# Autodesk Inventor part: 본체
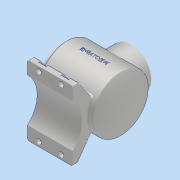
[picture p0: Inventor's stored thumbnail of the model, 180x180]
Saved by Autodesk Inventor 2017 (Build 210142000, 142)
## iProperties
Part Number: 본체
Material: 알루미늄 6061
Document SubType Name: Modeling
Designer: MRC
Density: 2.7 g/cm^3
Appearance: 알루미늄 - 평지
Mass: 1296.69 g
Surface Area: 1060.44 cm^2
Volume: 480.256 cm^3
Author: MRC
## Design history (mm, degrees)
sketch "스케치7"
  geometry: L1 (0, 0)-(120, 0); L2 (0, 0)-(0, 36); L3 (0, 36)-(12, 36); L4 (12, 36)-(12, 50); L5 (12, 50)-(108.336, 50); A1 r 113 centre (7, 0) between (120, 0) and (108.336, 50)
  constraints: 10 end point, 2 horizontal, 2 perpendicular, 2 point on circle, 1 centre point, 1 point on line, 1 vertical
  dimensions: "d11" = 120 distance of L1.start L1.end; "d12" = 72 diameter of L3 L1; "d13" = 100 diameter of L5 L1; "d14" = 113 radius of A1; "d15" = 12 distance of L2.end L3.end
revolve "회전1" sketch "스케치7" stored, may be unused: angle "d16" = 90 deg
revolve "회전2" stored, may be unused: angle "d22" = 90 deg
node "작업 평면1"
sketch "스케치9"
  geometry: C1 r 36 at (-62, 0); 1 further point
  constraints: 1 centre point, 1 horizontal alignment
  dimensions: "d24" = 72 diameter of C1; "d25" = 62 distance of point (0, 0) C1.centre
extrude "돌출2" join sketch "스케치9" stored distance "d26" = 12; taper "d27" = 0 deg
sketch "스케치10"
  geometry: C1 r 36 at (0, 0) reference; C2 r 27 at (0, 0); 1 further point
  constraints: 1 centre point, 1 coincident
  dimensions: "d28" = 54 diameter of C2
extrude "돌출3" cut sketch "스케치10" distance "d29" = 47.75; taper "d30" = 0 deg
sketch "스케치11"
  geometry: C1 r 27 at (0, 0) reference; 2 further points
  constraints: 1 vertical alignment
  dimensions: "d31" = 32.5 distance of point (0, 32.5) C1.centre
hole "구멍1" sketch "스케치11" at (0, 32.5) diameter "d32" = 3.242; stored, may be unused: countersink angle "d36" = 90 deg, drill point angle "d38" = 118 deg; dims "d33" = 8, "d34" = 4, "d35" = 2, "d37" = 10
node "작업 평면2"
sketch "스케치12"
  geometry: L1 (-42.278, -26.694)-(-67, -62); L2 (-67, -62)-(-77, -62); L3 (-77, -62)-(-77, 62); L4 (-77, 62)-(-67, 62); L5 (-67, 62)-(-42.278, 26.694); A1 r 50 centre (0, 0) between (-42.278, -26.694) and (-42.278, 26.694) reference; 1 further point
  constraints: 10 end point, 2 perpendicular, 2 point on circle, 1 horizontal
  dimensions: "d43" = 10 distance of L3.end L4.end; "d44" = 77 distance from line of L3 point (0, 0); "d45" = 10 distance of L1.end L2.end; "d46" = 55 deg angle of L4 L5; "d47" = 55 deg angle of L2 L1; "d48" = 124 distance of L2.end L3.end; "d49" = 62 vertical distance of L2.end point (0, 0)
extrude "돌출4" join sketch "스케치12" stored distance "d50" = 80; taper "d51" = 0 deg
sketch "스케치13"
  geometry: L1 (62, -77)-(-62, -77) reference; A1 r 52.096 centre (0, -112.096) between (38.5, -77) and (-38.5, -77); 1 further point
  constraints: 2 point on circle, 2 point on line, 1 centre point, 1 vertical alignment
  dimensions: "d52" = 17 distance edge to line of A1 L1; "d53" = 77 distance of A1.start A1.end
extrude "돌출5" cut sketch "스케치13" distance "d54" = 80; taper "d55" = 0 deg
sketch "스케치14"
  geometry: 2 further points
  constraints: 1 vertical alignment
  dimensions: "d56" = 32.5 distance of point (0, 32.5) point (0, 0)
hole "구멍2" sketch "스케치14" at (0, 32.5) diameter "d57" = 3.242; stored, may be unused: countersink angle "d61" = 90 deg, drill point angle "d63" = 118 deg; dims "d58" = 8, "d59" = 4, "d60" = 2, "d62" = 10
sketch "스케치15"
  geometry: L1 (80, 23.5)-(80, 0) reference; L2 (0, 0)-(80, 0) reference; C1 r 4.5 at (60, 8); 1 further point
  constraints: 1 centre point
  dimensions: "d67" = 9 diameter of C1; "d68" = 20 distance from line of C1.centre L1; "d69" = 8 distance from line of C1.centre L2
extrude "돌출6" cut sketch "스케치15" distance "d70" = 6; taper "d71" = 0 deg
sketch "스케치16"
  geometry: L1 (7, -8)-(7, 0); L2 (-7, 0)-(-7, -8); L3 (-7, -8)-(7, -8); L4 (-60, -8)-(20, -8) reference; C1 r 4.5 at (0, 0) reference; A1 r 7 centre (0, 0) between (7, 0) and (-7, 0); 1 further point
  constraints: 6 end point, 2 point on circle, 2 tangent, 1 centre point, 1 coincident, 1 perpendicular, 1 point on line, 1 vertical
  dimensions: "d89" = 14 distance of L2.end L1.start; "d90" = 7 radius of A1
extrude "돌출7" cut sketch "스케치16" distance "d73" = 27.5; taper "d74" = 0 deg
chamfer "모따기1" distance "d81" = 1; stored, may be unused: second distance "d82" = 2, angle "d83" = 45 deg
chamfer "모따기2" distance "d84" = 1; stored, may be unused: second distance "d85" = 2, angle "d86" = 45 deg
fillet "모깎기1" dims "d87" = 3
fillet "모깎기2" dims "d88" = 3
fillet "모깎기3" dims "d94" = 3
fillet "모깎기4" dims "d95" = 3
fillet "모깎기5" dims "d96" = 3
node "작업 평면3"
sketch "스케치17"
  geometry: L1 (0, -36)-(0, 36) reference; 3 further points
  constraints: 1 horizontal alignment, 1 midpoint, 1 other
  dimensions: "d98" = 62 distance from line of point (62, 0) L1
feature "엠보싱1" sketch "스케치17" dims "d11" = 120, "d12" = 72, "d13" = 100, "d14" = 113, "d15" = 12, "d99" = 0.5, "d100" = 0
fillet "모깎기6" dims "d103" = 3
node "솔리드2"
pattern_circular "원형 패턴1" dims angle "d40" = 360 deg
pattern_circular "원형 패턴2" dims angle "d65" = 360 deg
pattern_linear "직사각형 패턴2" dims "d93" = 40
mirror "미러1"
sketch "스케치8"
  geometry: L1 (0, 0)-(0, 27); L2 (0, -36)-(0, -36.043); L3 (0, 27)-(19, 27); L4 (19, 27)-(19, 43); L5 (19, 43)-(103.887, 43); L6 (0, 0)-(113, 0); L7 (0, -36)-(0, 36) reference; L8 (108.336, -50)-(108.336, 50) reference; A1 r 106 centre (7, 0) between (113, 0) and (103.887, 43); 3 further points
  constraints: 12 end point, 3 point on line, 2 horizontal, 2 perpendicular, 2 point on circle, 1 centre point, 1 coincident, 1 collinear, 1 midpoint
  dimensions: "d17" = 54 diameter of L3 L6; "d18" = 86 diameter of L5 L6; "d19" = 19 distance of L1.end L3.end; "d20" = 106 radius of A1; "d104" = 113 distance of L1.start L6.end
node "투영된 루프1"
node "투영된 루프2"
node "투영된 루프3"
other parameters: "d23" = 65, "d97" = 101
